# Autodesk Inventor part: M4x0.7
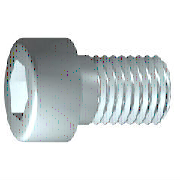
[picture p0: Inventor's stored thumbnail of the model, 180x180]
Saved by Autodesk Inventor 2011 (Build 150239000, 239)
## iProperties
IsCustomPart: 1
Created: 2009-02
Part Number: M4x0.7
Material: 강, 연강
Description: 6각머리 태핑 나사
Document SubType Name: Modeling
Standard: KS B 1003
Designer: SeoGD™[esajin.kr]
Standards Organization: KS
Language: ko-KR
Size Designation: M 4 x 16
Categories: <MemberInstance><Categories><Category DisplayName="조임쇠" InternalName="e4da775c-781d-43d5-af7c-5136215cf5a6" Mnemonic="FSTN"><Category DisplayName="볼트" InternalN
Density: 1 g/cm^3
Author: SeoGD™[esajin.kr]
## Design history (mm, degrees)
body "Solid1"
workplane "Work Plane1"
fillet "Fillet2" dims "d30" = 0.1 (= R)
revolve "본체" stored, may be unused: angle "d10" = 90 deg
sketch "스케치2"
  geometry: L1 (0, -4.9)-(0, 4.9) reference; L2 (-4.9, 0)-(4.9, 0) reference; L3 (1.732, 0)-(0.866, -1.5); L4 (0.866, -1.5)-(-0.866, -1.5); L5 (-0.866, -1.5)-(-1.732, 0); L6 (-1.732, 0)-(-0.866, 1.5); L7 (-0.866, 1.5)-(0.866, 1.5); L8 (0.866, 1.5)-(1.732, 0); 2 further points
  constraints: 12 end point, 1 coincident, 1 horizontal alignment, 1 point on line, 12 other
extrude "슬롯" join sketch "스케치2" stored distance "d11" = 10; taper "d12" = 0 deg
fillet "모깎기1" dims "d17" = 0.4 (= RR)
feature "스레드" dims "d13" = 14.25 (= GEL), "d14" = 0
chamfer "모따기1" distance "d15" = 0.42941 (= -0.5 x SPD + 0.5 x GD); stored, may be unused: second distance "d16" = 0.42941 (= GUL), angle "d27" = 45 deg
sketch "스케치1"
  geometry: L1 (-1, 0)-(16, 0); L2 (16, 0)-(16, 2); L3 (16, 2)-(1.75, 2); L4 (1.75, 2)-(1.32, 2); L5 (1.32, 2)-(0, 2); L6 (0, 2)-(0, 3.5); L7 (0, 3.5)-(-4, 3.5); L8 (-4, 3.5)-(-4, 1.732); L9 (-4, 1.732)-(-2, 1.732); L10 (-2, 1.732)-(-1, 0); L11 (-8, 0)-(20, 0) reference; L12 (0, -0.7)-(0, 4.2) reference; L13 (1.75, 2)-(0, 2)
  constraints: 22 end point, 6 parallel, 2 collinear, 2 perpendicular, 1 horizontal, 1 point on line
  dimensions: "d1" = 14.25 distance from line of L3.end L2 (= GEL); "d2" = 0.42952 distance of L4.end L3.end (computed from GAL); "d3" = 4 distance between parallel lines of L8 L6 (= KOH); "d4" = 2 distance of L8.end L9.end (= INTI); "d5" = 60 deg angle of L10 L1; "d6" = 4 diameter of L3 L1 (= GD); "d7" = 4 diameter of L5 L1 (= BDM); "d8" = 3.4641 diameter of L9 L1 (= 1.1547 x SW); "d9" = 7 diameter of L7 L1 (= KOD); "d26" = 16 distance between parallel lines of L12 L2 (= NLG)
other parameters: "GD" = 4 (= NND) [user parameter; used in 2 equation terms], "NLG" = 16 [user parameter; used in 1 equation term], "GEL" = 14.25 [user parameter; used in 2 equation terms], "KOD" = 7 [user parameter; used in 1 equation term], "KOH" = 4 [user parameter; used in 1 equation term], "INTI" = 2 [user parameter; used in 1 equation term], "GAL" = 0.42941 (= 0.61345 x PTC) [user parameter; used in 1 equation term], "GUL" = 0.42941 (= 0.61345 x PTC) [user parameter; used in 1 equation term], "BDM" = 4 (= NND) [user parameter; used in 1 equation term], "SW" = 3 [user parameter; used in 2 equation terms], "RR" = 0.4 [user parameter; used in 1 equation term], "SPD" = 3.14117 (= NND - 1.2269 x PTC) [user parameter; used in 1 equation term], "d19" = 0, "d28" = 0, "d29" = 0, "R" = 0.1 [user parameter; used in 1 equation term], "PHH" = 0.2 [user parameter], "GD1" = 3.14117 (= THREADDIA - 1.2269 x PTC) [user parameter], "THREADDIA" = 4 [user parameter; used in 1 equation term], "FAWI" = 45 deg [user parameter], "TPU" = 14.28571 (computed from PTC) [user parameter], "PTC" = 0.7 [user parameter; used in 5 equation terms], "NND" = 4 [user parameter; used in 3 equation terms], "TOA" = 30 deg [user parameter], "E0" = 3.465 (= 1.155 x SW) [user parameter]
